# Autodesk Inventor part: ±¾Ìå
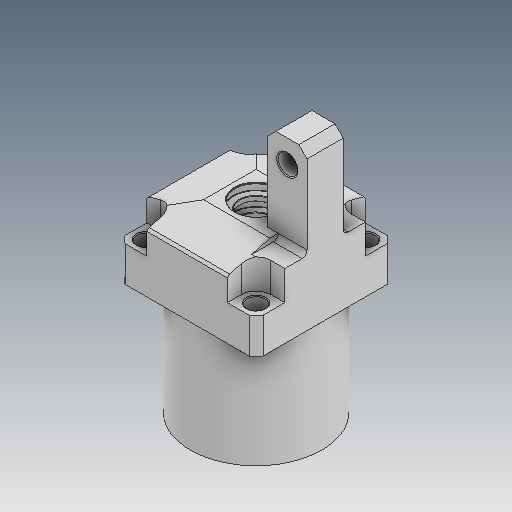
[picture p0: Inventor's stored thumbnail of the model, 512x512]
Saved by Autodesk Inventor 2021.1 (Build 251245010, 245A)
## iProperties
Created: 2013-04
Part Number: ±¾Ìå
Material: Ogólny
Document SubType Name: Modeling
Designer: user
Density: 1 g/cm^3
Appearance: Domyślna
Author: user
Revision Number: ÈÎºÎ
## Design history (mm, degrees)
feature "µ¹½Ç11"
node "Bryła1"
